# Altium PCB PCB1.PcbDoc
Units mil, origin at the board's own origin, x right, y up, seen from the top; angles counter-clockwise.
Board outline 6000 x 4000 mil, 2 copper layers (Top Layer, Bottom Layer); 15 components, 11 nets, 37 pads, 0 vias.
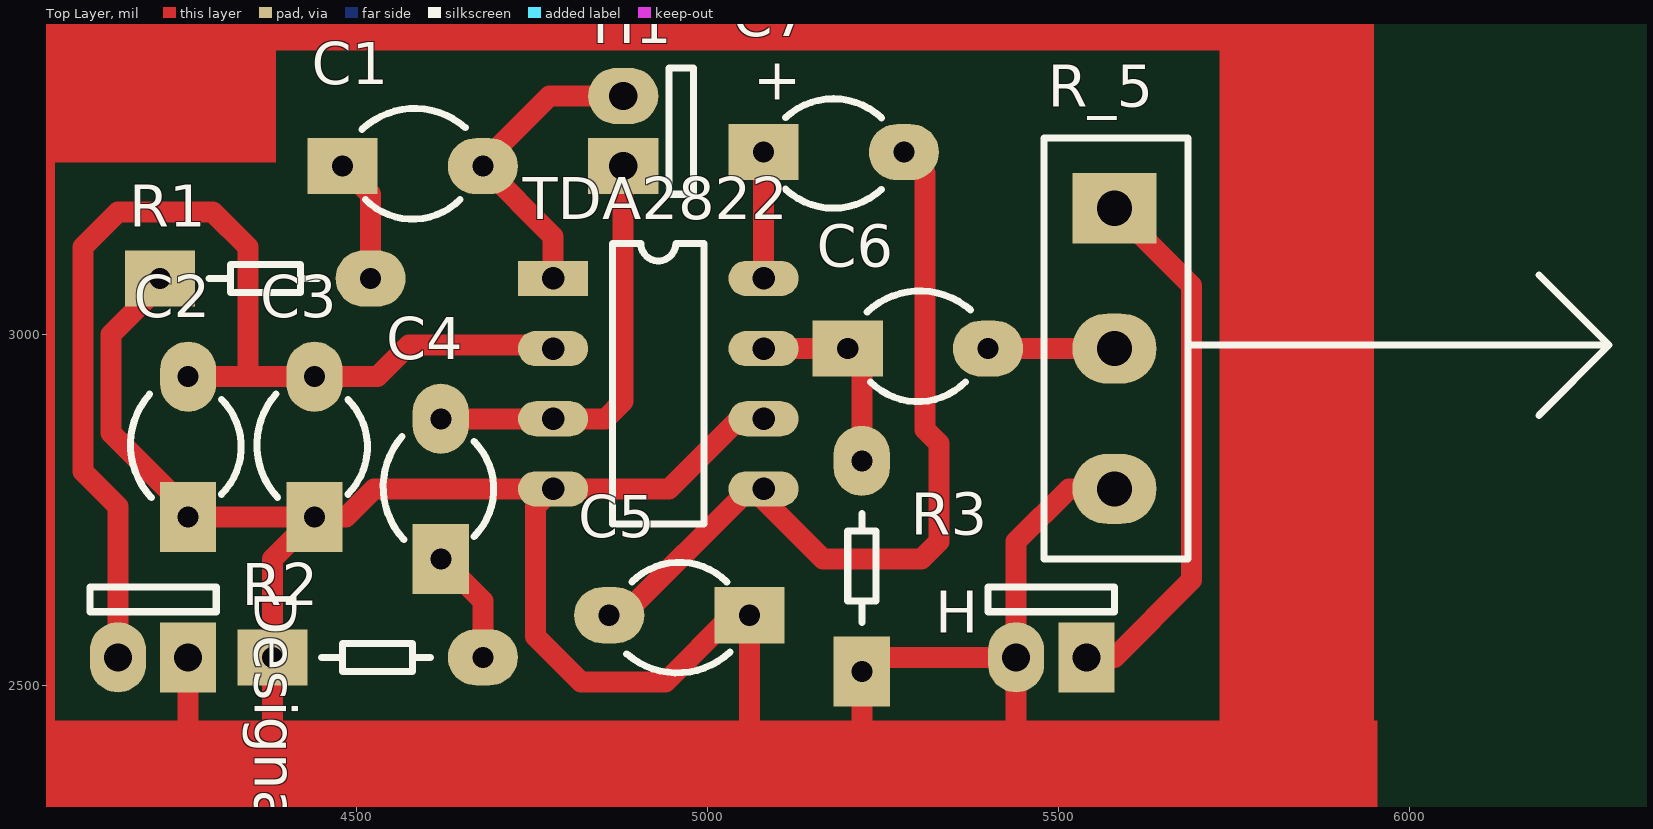
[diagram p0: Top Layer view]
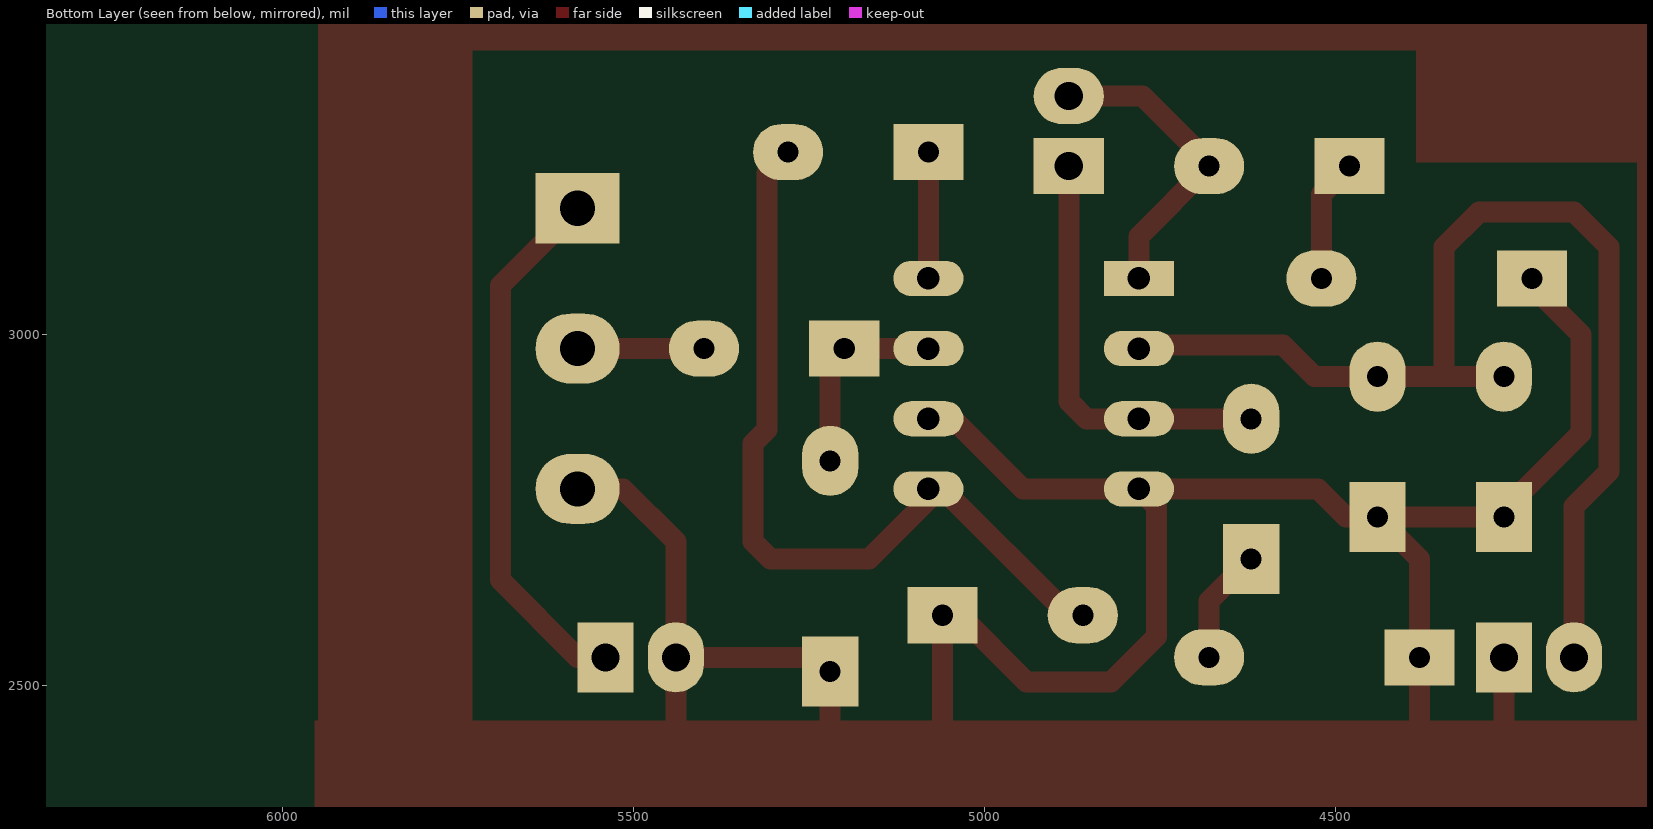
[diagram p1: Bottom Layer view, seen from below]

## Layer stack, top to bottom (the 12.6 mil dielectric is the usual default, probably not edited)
Top Layer: signal copper 1.4
Dielectric: dielectric 12.6, FR-4, Dk 4.8
Bottom Layer: signal copper 1.4

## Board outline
1000,1000 7000,1000 7000,5000 1000,5000

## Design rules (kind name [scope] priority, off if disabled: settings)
Clearance [All] p1: gap=10
ComponentClearance [All] p1: gap=10 collisioncheckmode=0
PolygonConnect [All] p1: connectstyle=Relief reliefconductorwidth=10 reliefentries=4 polygonreliefangle="90 Angle"
RoutingVias [All] p1: holewidth=28 width=50 viastyle="Through Hole" minholewidth=28 minwidth=50 maxholewidth=28 maxwidth=50
SolderMaskExpansion [All] p1: expansion=4
TestPointUsage [All] p1: valid=0 allowmultiple=FALSE
Testpoint [All] p1: side=15 testpointundercomponent=TRUE minsize=40 maxsize=100 preferedsize=60 minholesize=0 maxholesize=40 preferedholesize=32 testpointgrid=1 style=1023 order=-539222988
Width [All] p1: maxlimit=30 minlimit=10 preferedwidth=10 toplayer_minwidth=20 toplayer_prefwidth=30 bottomlayer_minwidth=20 bottomlayer_prefwidth=30 minimp=50.000000 maximp=50.000000 favimp=50.000000
17 further rules are at their usual default settings.

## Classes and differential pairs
component class 功放: C1 C2 C3 C4 C5 C6 C7 H H1 R1 R2 R3 R_5 TDA2822

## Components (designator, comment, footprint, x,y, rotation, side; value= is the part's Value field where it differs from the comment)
C1 "CC1" C2 4580,3140 r0 top
C2 "CC1" C2 4360,2840 r90 top
C3 "CC1" C2 4540,2840 r90 top
C4 "CC1" C2 4720,2780 r90 top
C5 "CC1" C2 4960,2700 r180 top
C6 "CC1" C2 5300,2880 r0 top
C7 "CC2" CC1+ 5180,3160 r0 top
Designator1 "Comment" H2 4160,2540 r270 top
H "H2" H2 5440,2540 r270 top
H1 "H2" H2 4880,3340 r180 top
R1 "R_4" RR1 4320,2980 r0 top
R2 "R_4" RR1 4480,2440 r0 top
R3 "R_4" RR1 5320,2620 r90 top
R_5 "R_DB2" RD_B 5580,2980 r0 top
TDA2822 "DIP8" DIP8 4780,3080 r0 top

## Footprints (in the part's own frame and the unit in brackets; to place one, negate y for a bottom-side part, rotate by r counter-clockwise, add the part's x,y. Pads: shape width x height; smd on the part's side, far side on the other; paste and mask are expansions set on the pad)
C2 [mil] "电容2"
  rect 100x80 hole 30: 1(-100,100)
  oval 100x80 hole 30: 2(100,100)
  silkscreen extent -72,25 75,182
CC1+ [mil]
  rect 100x80 hole 30: 1(-100,100)
  oval 100x80 hole 30: 2(100,100)
  silkscreen extent -69,20 68,176
DIP8 [mil]
  rect 100x50 hole 32: 1(0,0)
  oval 100x50 hole 32: 2(0,-100) 3(0,-200) 4(0,-300) 5(300,-300) 6(300,-200) 7(300,-100) 8(300,0)
  silkscreen extent 85,-350 215,50
H2 [mil]
  rect 100x80 hole 40: 1(0,100)
  oval 100x80 hole 40: 2(0,0)
  silkscreen extent -100,-40 -65,140
RD_B [mil] "滑动变阻器"
  rect 120x100 hole 50: 1(0,200)
  oval 120x100 hole 50: 2(0,0) 3(0,-200)
  silkscreen extent -100,-300 705,300
RR1 [mil] "电阻3"
  rect 100x80 hole 30: 1(-100,100)
  oval 100x80 hole 30: 2(200,100)
  silkscreen extent -30,80 125,120

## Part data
C1 C2 C3 C4 C5 C6: "电容"
C7: "电解电容"
Designator1: library part H2
R1 R2 R3: library part RR2
TDA2822: "оƬ"

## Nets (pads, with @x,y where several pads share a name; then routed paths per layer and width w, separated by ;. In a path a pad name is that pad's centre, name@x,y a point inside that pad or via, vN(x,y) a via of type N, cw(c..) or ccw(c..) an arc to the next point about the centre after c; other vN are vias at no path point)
GND: C2.1 C3.1 C5.1 Designator1.1 H.2 R1.1 R2.1 R3.1 R_5.3 TDA2822.4 TDA2822.6 | length 3413.4
  Top Layer w30: R1.1 4220,3070 4150,3000 4150,2860 4260,2750 C2.1 4485,2740 4525,2780 4945,2780 5045,2880 TDA2822.6 ; 4260,2405 Designator1.1 ; 4380,2430 4380,2680 C3.1 ; TDA2822.4 4755,2755 4755,2570 4820,2505 4940,2505 5035,2600 C5.1 5060,2385 ; 5220,2380 R3.1 5240,2540 H.2 ; 5440,2400 5440,2705 5515,2780 R_5.3
NetC1_1: C1.1 R1.2 | length 176.6
  Top Layer w30: C1.1 4520,3200 R1.2
NetC1_2: C1.2 H1.2 TDA2822.1 | length 445.8
  Top Layer w30: TDA2822.1 4780,3140 C1.2 4680,3245 4775,3340 H1.2
NetC4_1: C4.1 R2.2 | length 164.9
  Top Layer w30: C4.1 4680,2620 R2.2
NetC4_2: C4.2 H1.1 TDA2822.3 | length 605.4
  Top Layer w30: C4.2 4855,2880 4880,2905 H1.1
NetC5_2: C5.2 C7.2 TDA2822.5 | length 1180.8
  Top Layer w30: C5.2 4880,2600 5060,2780 TDA2822.5 5080,2765 5165,2680 5305,2680 5330,2705 5330,2845 5310,2865 5310,3230 C7.2
NetC6_1: C6.1 R3.2 TDA2822.7 | length 288.3
  Top Layer w30: TDA2822.7 C6.1 5220,2960 R3.2
NetC6_2: C6.2 R_5.2 | length 180
  Top Layer w30: C6.2 R_5.2
NetC7_1: C7.1 TDA2822.8 | length 180
  Top Layer w30: TDA2822.8 C7.1
NetH_1: H.1 R_5.1 | length 771.1
  Top Layer w30: H.1 5580,2540 5690,2650 5690,3070 R_5.1
VCC: C2.2 C3.2 Designator1.2 TDA2822.2 | length 1607.8
  Top Layer w30: Designator1.2 4160,2755 4110,2805 4110,3125 4160,3175 4295,3175 4345,3125 4345,2940 ; C2.2 4530,2940 4575,2985 4775,2985 TDA2822.2

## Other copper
Top Layer:
  rectangle net GND: 3990,3245 4385,3440
  rectangle net GND: 3795,2150 4070,3565
  rectangle net GND: 3850,3405 5930,3565
  rectangle net GND: 5730,2380 5950,3560
  rectangle net GND: 3960,2155 5955,2450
